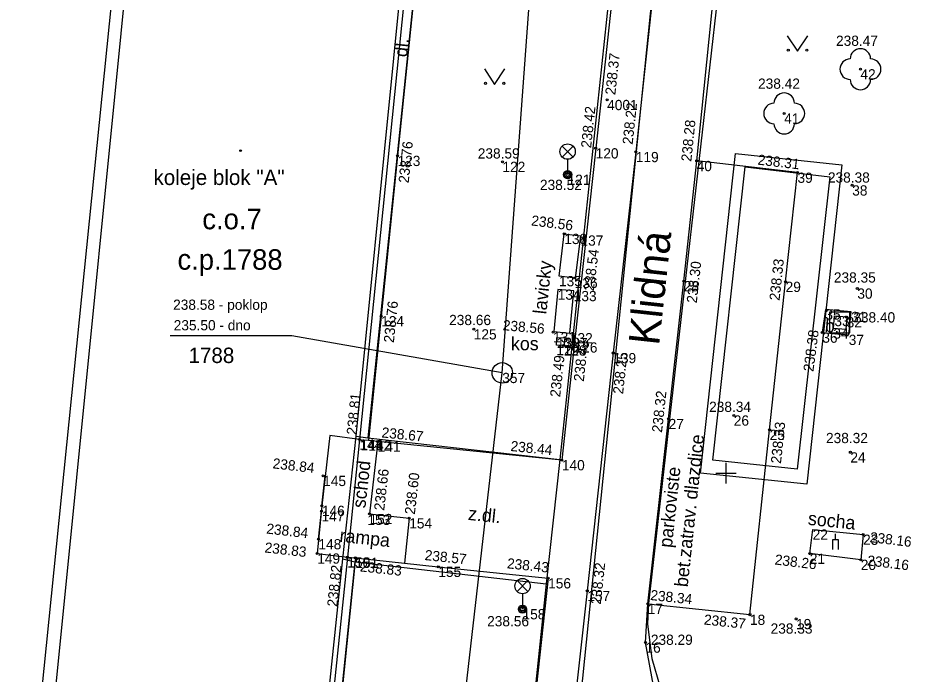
# Model space of a CAD drawing. Extents: x -596309 to -596099, y -1158697 to -1158513.
# Drawn here: x -596284.56 to -596240.96, y -1158609.82 to -1158577.76 of the extents above; entities that cross this region are included whole.
import ezdxf

# ---------------------------------------------------------------- set-up
doc = ezdxf.new("R2010")
doc.units = 0
for name, color, linetype in [('Vrstva 1', 7, 'Continuous'), ('Vrstva 10', 7, 'Continuous'), ('Vrstva 11', 7, 'Continuous'), ('Vrstva 14', 7, 'Continuous'), ('Vrstva 2', 7, 'Continuous'), ('Vrstva 22', 7, 'Continuous'), ('Vrstva 26', 7, 'Continuous'), ('Vrstva 27', 7, 'Continuous'), ('Vrstva 3', 7, 'Continuous'), ('Vrstva 33', 7, 'Continuous'), ('Vrstva 36', 7, 'Continuous'), ('Vrstva 38', 7, 'Continuous'), ('Vrstva 39', 7, 'Continuous'), ('Vrstva 40', 7, 'Continuous'), ('Vrstva 41', 7, 'Continuous'), ('Vrstva 46', 7, 'Continuous'), ('Vrstva 47', 7, 'Continuous'), ('Vrstva 49', 7, 'Continuous'), ('Vrstva 5', 7, 'Continuous'), ('Vrstva 58', 7, 'Continuous'), ('Vrstva 59', 7, 'Continuous'), ('Vrstva 60', 7, 'Continuous'), ('Vrstva 61', 7, 'Continuous'), ('Vrstva 8', 7, 'Continuous')]:
    doc.layers.add(name, color=color, linetype=linetype)

msp = doc.modelspace()

# ---------------------------------------------------------------- linework, layer by layer
at = {"layer": 'Vrstva 1'}
for p, q in [((-596284.56, -1158622.27), (-596277.87, -1158556.03)), ((-596263.44, -1158559.15), (-596267.48, -1158598.27)), ((-596254.63, -1158566.54), (-596258.11, -1158599.33)), ((-596252.59, -1158566.74), (-596260.61, -1158645.31)), ((-596253.77, -1158606.37), (-596250.06, -1158573.78)), ((-596251.25, -1158600), (-596249.54, -1158584.38)), ((-596249.54, -1158584.38), (-596244.34, -1158584.94)), ((-596250.64, -1158599.37), (-596249.07, -1158585.04)), ((-596249.07, -1158585.04), (-596244.94, -1158585.52)), ((-596244.34, -1158584.94), (-596246.05, -1158600.53)), ((-596244.94, -1158585.52), (-596246.53, -1158599.81)), ((-596268.05, -1158598.2), (-596267.48, -1158598.27)), ((-596267.48, -1158598.27), (-596258.11, -1158599.33)), ((-596258.11, -1158599.33), (-596258.77, -1158605.41)), ((-596246.53, -1158599.81), (-596250.64, -1158599.37)), ((-596246.05, -1158600.53), (-596251.25, -1158600)), ((-596268.11, -1158604.33), (-596270.4, -1158626.69)), ((-596268.7, -1158604.18), (-596268.11, -1158604.33)), ((-596268.11, -1158604.33), (-596258.77, -1158605.41)), ((-596258.77, -1158605.41), (-596262.89, -1158644.39)), ((-596253.81, -1158607.36), (-596253.77, -1158606.37)), ((-596253.61, -1158609.06), (-596253.81, -1158607.36)), ((-596253.2, -1158610.47), (-596253.61, -1158609.06))]:
    msp.add_line(p, q, dxfattribs=at)
msp.add_lwpolyline([(-596270.97, -1158626.01), (-596268.7, -1158604.18), (-596268.05, -1158598.2), (-596264.37, -1158561.26), (-596268.27, -1158560.79), (-596268.03, -1158558.14), (-596277.39, -1158556.98), (-596283.84, -1158621.73)], dxfattribs=at)
at = {"layer": 'Vrstva 10'}
for points in [[(-596255.23, -1158545.06), (-596254.2, -1158547.01), (-596253.17, -1158550.76), (-596252.36, -1158555.01), (-596251.99, -1158558.97), (-596251.94, -1158561.36), (-596252.44, -1158566.04), (-596253.24, -1158573.57), (-596254.4, -1158584.31), (-596255.5, -1158594.13), (-596256.77, -1158605.75), (-596257.81, -1158615.11), (-596258.65, -1158622.97), (-596259.56, -1158631.31), (-596260.07, -1158635.97)], [(-596253.51, -1158610.57), (-596253.93, -1158608.27), (-596253.82, -1158606.38), (-596248.83, -1158606.91), (-596247.87, -1158597.88), (-596247.09, -1158590.65), (-596246.51, -1158585.32), (-596251.43, -1158584.75), (-596250.33, -1158573.96), (-596250.2, -1158572.65), (-596249.12, -1158563.05), (-596248.35, -1158556.12), (-596248.08, -1158555.05), (-596247.42, -1158553.82), (-596246.81, -1158553.02), (-596245.52, -1158551.57), (-596243.33, -1158550.18), (-596240.98, -1158549.46)]]:
    msp.add_lwpolyline(points, dxfattribs=at)
at = {"layer": 'Vrstva 11'}
for p, q in [((-596267.45, -1158598.4), (-596267.84, -1158598.38)), ((-596265.46, -1158602.2), (-596265.697, -1158604.39)), ((-596268.48, -1158604.11), (-596268.09, -1158604.13))]:
    msp.add_line(p, q, dxfattribs=at)
for points in [[(-596264.269, -1158561.096), (-596264.23, -1158559.86), (-596261.45, -1158560.17), (-596260.93, -1158560.92), (-596259.93, -1158560.98), (-596259.85, -1158560.33), (-596254.02, -1158560.92), (-596254.46, -1158565.92), (-596255.2, -1158573.41), (-596256.36, -1158584.13), (-596257.39, -1158593.61), (-596258.01, -1158599.36), (-596267, -1158598.45), (-596267.45, -1158598.4)], [(-596264.12, -1158561.11), (-596263.62, -1158561.23), (-596264.07, -1158565.05), (-596264.83, -1158572.78), (-596266.03, -1158584.5), (-596266.83, -1158592.33), (-596267.45, -1158598.4)], [(-596253.82, -1158606.38), (-596252.8, -1158597.35), (-596252.06, -1158590.62), (-596251.43, -1158584.75)], [(-596267, -1158598.45), (-596267.4, -1158601.99), (-596265.46, -1158602.2)], [(-596268.09, -1158604.13), (-596269.05, -1158613.79), (-596269.79, -1158621.23), (-596270.48, -1158628.13), (-596269.54, -1158628.22), (-596270.08, -1158633.46)], [(-596268.09, -1158604.13), (-596264.04, -1158604.57), (-596258.68, -1158605.13), (-596259.74, -1158614.86), (-596260.55, -1158622.72), (-596261.59, -1158631.85), (-596261.81, -1158634.02), (-596262.2, -1158634.28), (-596265.1, -1158634.02), (-596270.08, -1158633.46)]]:
    msp.add_lwpolyline(points, dxfattribs=at)
for points in [[(-596258.15, -1158590.37), (-596257.89, -1158588.31), (-596257.102, -1158588.409), (-596257.362, -1158590.469)], [(-596257.62, -1158593.16), (-596257.43, -1158591.1), (-596258.21, -1158591.028), (-596258.4, -1158593.088)], [(-596243.89, -1158592.12), (-596245.15, -1158592), (-596245.3, -1158593.13), (-596244.01, -1158593.24)], [(-596257.87, -1158593.39), (-596257.92, -1158593.76), (-596258.28, -1158593.74), (-596258.26, -1158593.38)], [(-596243.42, -1158604.23), (-596245.91, -1158603.93), (-596245.77, -1158602.75), (-596243.31, -1158603)]]:
    msp.add_lwpolyline(points, close=True, dxfattribs=at)
at = {"layer": 'Vrstva 2'}
msp.add_lwpolyline([(-596260.92, -1158595.1), (-596271.183, -1158593.285), (-596277.122, -1158593.285)], dxfattribs=at)
for centre in [(-596243.44, -1158580.27), (-596255.8, -1158581.77), (-596247.16, -1158582.43), (-596266.03, -1158584.5), (-596256.36, -1158584.13), (-596254.4, -1158584.31), (-596260.91, -1158584.79), (-596251.43, -1158584.75), (-596246.51, -1158585.32), (-596243.84, -1158585.94), (-596257.89, -1158588.31), (-596257.38, -1158590.46), (-596252.06, -1158590.62), (-596247.09, -1158590.65), (-596243.59, -1158590.98), (-596266.83, -1158592.33), (-596244.11, -1158592.38), (-596262.31, -1158592.97), (-596258.44, -1158593.11), (-596245.3, -1158593.13), (-596257.39, -1158593.61), (-596257.92, -1158593.76), (-596255.5, -1158594.13), (-596252.8, -1158597.35), (-596249.62, -1158597.18), (-596247.87, -1158597.88), (-596267.89, -1158598.35), (-596267, -1158598.45), (-596243.93, -1158598.98), (-596258.01, -1158599.36), (-596269.66, -1158600.13), (-596269.74, -1158601.86), (-596269.72, -1158601.59), (-596267.4, -1158601.99), (-596265.46, -1158602.2), (-596269.89, -1158603.22), (-596243.31, -1158603), (-596269.95, -1158603.92), (-596268.48, -1158604.11), (-596268.09, -1158604.13), (-596245.91, -1158603.93), (-596264.04, -1158604.57), (-596243.42, -1158604.23), (-596258.68, -1158605.13), (-596256.77, -1158605.75), (-596253.82, -1158606.38), (-596248.83, -1158606.91), (-596246.58, -1158607.12), (-596253.93, -1158608.27)]:
    msp.add_circle(centre, 0.05, dxfattribs=at)
at = {"layer": 'Vrstva 22'}
for centre in [(-596243.44, -1158580.27), (-596247.16, -1158582.43)]:
    msp.add_circle(centre, 0.05, dxfattribs=at)
for centre, start, end in [((-596243.44, -1158579.77), 0, 180), ((-596243.94, -1158580.27), 90, 270), ((-596242.94, -1158580.27), 270, 90), ((-596243.44, -1158580.77), 180, 0), ((-596247.16, -1158581.93), 0, 180), ((-596247.66, -1158582.43), 90, 270), ((-596246.66, -1158582.43), 270, 90), ((-596247.16, -1158582.93), 180, 0)]:
    msp.add_arc(centre, 0.5, start, end, dxfattribs=at)
at = {"layer": 'Vrstva 26'}
msp.add_lwpolyline([(-596244.955, -1158593.14), (-596243.955, -1158593.14), (-596243.955, -1158592.14), (-596244.955, -1158592.14)], close=True, dxfattribs=at)
at = {"layer": 'Vrstva 27'}
msp.add_circle((-596260.92, -1158595.1), 0.5, dxfattribs=at)
at = {"layer": 'Vrstva 3'}
for p, q in [((-596243.44, -1158580.27), (-596243.439, -1158580.27)), ((-596255.8, -1158581.77), (-596255.799, -1158581.77)), ((-596247.16, -1158582.43), (-596247.159, -1158582.43)), ((-596256.36, -1158584.13), (-596256.359, -1158584.13)), ((-596254.4, -1158584.31), (-596254.399, -1158584.31)), ((-596266.03, -1158584.5), (-596266.029, -1158584.5)), ((-596260.91, -1158584.79), (-596260.909, -1158584.79)), ((-596251.43, -1158584.75), (-596251.429, -1158584.75)), ((-596246.51, -1158585.32), (-596246.509, -1158585.32)), ((-596257.73, -1158585.42), (-596257.729, -1158585.42)), ((-596243.84, -1158585.94), (-596243.839, -1158585.94)), ((-596257.89, -1158588.31), (-596257.889, -1158588.31)), ((-596257.1, -1158588.39), (-596257.099, -1158588.39)), ((-596258.15, -1158590.37), (-596258.149, -1158590.37)), ((-596257.38, -1158590.46), (-596257.379, -1158590.46)), ((-596252.06, -1158590.62), (-596252.059, -1158590.62)), ((-596247.09, -1158590.65), (-596247.089, -1158590.65)), ((-596243.59, -1158590.98), (-596243.589, -1158590.98)), ((-596258.21, -1158591.03), (-596258.209, -1158591.03)), ((-596257.43, -1158591.1), (-596257.429, -1158591.1)), ((-596245.15, -1158592), (-596245.149, -1158592)), ((-596243.89, -1158592.12), (-596243.889, -1158592.12)), ((-596266.83, -1158592.33), (-596266.829, -1158592.33)), ((-596244.71, -1158592.32), (-596244.709, -1158592.32)), ((-596244.11, -1158592.38), (-596244.109, -1158592.38)), ((-596262.31, -1158592.97), (-596262.309, -1158592.97)), ((-596258.44, -1158593.11), (-596258.439, -1158593.11)), ((-596257.62, -1158593.16), (-596257.619, -1158593.16)), ((-596245.3, -1158593.13), (-596245.299, -1158593.13)), ((-596244.76, -1158592.93), (-596244.759, -1158592.93)), ((-596258.26, -1158593.38), (-596258.259, -1158593.38)), ((-596257.87, -1158593.39), (-596257.869, -1158593.39)), ((-596257.39, -1158593.61), (-596257.389, -1158593.61)), ((-596244.01, -1158593.24), (-596244.009, -1158593.24)), ((-596258.28, -1158593.74), (-596258.279, -1158593.74)), ((-596257.92, -1158593.76), (-596257.919, -1158593.76)), ((-596255.5, -1158594.13), (-596255.499, -1158594.13)), ((-596260.92, -1158595.1), (-596260.919, -1158595.1)), ((-596260.92, -1158595.1), (-596260.919, -1158595.1)), ((-596252.8, -1158597.35), (-596252.799, -1158597.35)), ((-596249.62, -1158597.18), (-596249.619, -1158597.18)), ((-596247.87, -1158597.88), (-596247.869, -1158597.88)), ((-596267.89, -1158598.35), (-596267.889, -1158598.35)), ((-596267.84, -1158598.38), (-596267.839, -1158598.38)), ((-596267.45, -1158598.4), (-596267.449, -1158598.4)), ((-596267, -1158598.45), (-596266.999, -1158598.45)), ((-596243.93, -1158598.98), (-596243.929, -1158598.98)), ((-596258.01, -1158599.36), (-596258.009, -1158599.36)), ((-596269.66, -1158600.13), (-596269.659, -1158600.13)), ((-596269.74, -1158601.86), (-596269.739, -1158601.86)), ((-596269.72, -1158601.59), (-596269.719, -1158601.59)), ((-596267.5, -1158602.03), (-596267.499, -1158602.03)), ((-596267.4, -1158601.99), (-596267.399, -1158601.99)), ((-596265.46, -1158602.2), (-596265.459, -1158602.2)), ((-596245.77, -1158602.75), (-596245.769, -1158602.75)), ((-596243.31, -1158603), (-596243.309, -1158603)), ((-596269.89, -1158603.22), (-596269.889, -1158603.22)), ((-596269.95, -1158603.92), (-596269.949, -1158603.92)), ((-596245.91, -1158603.93), (-596245.909, -1158603.93)), ((-596268.48, -1158604.11), (-596268.479, -1158604.11)), ((-596268.09, -1158604.13), (-596268.089, -1158604.13)), ((-596243.42, -1158604.23), (-596243.419, -1158604.23)), ((-596264.04, -1158604.57), (-596264.039, -1158604.57)), ((-596258.68, -1158605.13), (-596258.679, -1158605.13)), ((-596256.77, -1158605.75), (-596256.769, -1158605.75)), ((-596259.93, -1158606.64), (-596259.929, -1158606.64)), ((-596253.82, -1158606.38), (-596253.819, -1158606.38)), ((-596248.83, -1158606.91), (-596248.829, -1158606.91)), ((-596246.58, -1158607.12), (-596246.579, -1158607.12)), ((-596253.93, -1158608.27), (-596253.929, -1158608.27))]:
    msp.add_line(p, q, dxfattribs=at)
at = {"layer": 'Vrstva 33'}
for p, q in [((-596257.995, -1158584.56), (-596257.465, -1158584.03)), ((-596257.995, -1158584.03), (-596257.465, -1158584.56)), ((-596257.73, -1158584.67), (-596257.73, -1158585.42)), ((-596260.195, -1158605.78), (-596259.665, -1158605.25)), ((-596260.195, -1158605.25), (-596259.665, -1158605.78)), ((-596259.93, -1158605.89), (-596259.93, -1158606.64))]:
    msp.add_line(p, q, dxfattribs=at)
for centre, radius in [((-596257.73, -1158584.295), 0.375), ((-596257.73, -1158585.42), 0.2), ((-596257.73, -1158585.42), 0.145), ((-596257.73, -1158585.42), 0.0876), ((-596259.93, -1158605.515), 0.375), ((-596259.93, -1158606.64), 0.2), ((-596259.93, -1158606.64), 0.145), ((-596259.93, -1158606.64), 0.0876)]:
    msp.add_circle(centre, radius, dxfattribs=at)
at = {"layer": 'Vrstva 36'}
for points in [[(-596247.008, -1158578.638), (-596246.508, -1158579.388), (-596246.008, -1158578.638)], [(-596261.79, -1158580.259), (-596261.29, -1158581.009), (-596260.79, -1158580.259)]]:
    msp.add_lwpolyline(points, dxfattribs=at)
for centre in [(-596246.959, -1158579.338), (-596246.059, -1158579.338), (-596261.74, -1158580.959), (-596260.841, -1158580.959)]:
    msp.add_circle(centre, 0.05, dxfattribs=at)
at = {"layer": 'Vrstva 38'}
msp.add_line((-596244.654, -1158603.233), (-596244.654, -1158602.968), dxfattribs=at)
msp.add_lwpolyline([(-596244.779, -1158603.733), (-596244.779, -1158603.233), (-596244.529, -1158603.233), (-596244.529, -1158603.733)], dxfattribs=at)
at = {"layer": 'Vrstva 39'}
for radius in [0.045, 0.0199]:
    msp.add_circle((-596273.69, -1158584.248), radius, dxfattribs=at)
at = {"layer": 'Vrstva 5'}
msp.add_line((-596267.89, -1158598.35), (-596268.48, -1158604.11), dxfattribs=at)
msp.add_lwpolyline([(-596269.438, -1158560.623), (-596264.12, -1158561.11), (-596267.89, -1158598.35), (-596269.33, -1158598.167), (-596269.72, -1158601.59), (-596269.95, -1158603.92), (-596268.48, -1158604.11), (-596270.74, -1158625.83), (-596270.81, -1158625.81), (-596271.53, -1158633.35), (-596276.188, -1158632.886)], dxfattribs=at)
at = {"layer": 'Vrstva 58'}
msp.add_lwpolyline([(-596244.76, -1158592.93), (-596244.71, -1158592.32), (-596244.109, -1158592.369), (-596244.159, -1158592.979)], close=True, dxfattribs=at)
at = {"layer": 'Vrstva 60'}
msp.add_lwpolyline([(-596247.668, -1158643.114), (-596265.091, -1158631.45), (-596260.921, -1158595.1), (-596258.491, -1158561.83), (-596276.3, -1158553.438)], dxfattribs=at)
at = {"layer": 'Vrstva 61'}
for p, q in [((-596250, -1158599.5), (-596250, -1158600.5)), ((-596250.5, -1158600), (-596249.5, -1158600))]:
    msp.add_line(p, q, dxfattribs=at)
at = {"layer": 'Vrstva 8'}
for p, q in [((-596269.72, -1158601.59), (-596269.56, -1158600.138)), ((-596269.89, -1158603.22), (-596269.74, -1158601.86))]:
    msp.add_line(p, q, dxfattribs=at)

# ---------------------------------------------------------------- texts
at = {"layer": 'Vrstva 1'}
msp.add_text('357', height=0.5, dxfattribs=at).set_placement((-596260.92, -1158595.6))
at = {"layer": 'Vrstva 14'}
msp.add_text('1788', height=0.75, dxfattribs=at).set_placement((-596276.23, -1158594.62))
at = {"layer": 'Vrstva 2'}
for s, p in [('238.47', (-596244.63, -1158579.13)), ('238.42', (-596248.436, -1158581.225)), ('238.59', (-596262.114, -1158584.633)), ('238.38', (-596245.026, -1158585.808)), ('238.52', (-596259.08, -1158586.17)), ('238.35', (-596244.735, -1158590.691)), ('238.58 - poklop', (-596276.983, -1158592.022)), ('238.66', (-596263.512, -1158592.768)), ('238.40', (-596243.789, -1158592.64)), ('235.50 - dno', (-596276.954, -1158593.024)), ('238.34', (-596250.824, -1158597.007)), ('238.32', (-596245.12, -1158598.533)), ('238.56', (-596261.657, -1158607.481)), ('238.33', (-596247.823, -1158607.838)), ('238.29', (-596253.666, -1158608.385))]:
    msp.add_text(s, height=0.5, dxfattribs=at).set_placement(p)
for s, rotation, p in [('238.37', 83.8241, (-596255.403, -1158581.546)), ('238.42', 83.8241, (-596256.586, -1158584.141)), ('238.22', 83.8355, (-596254.559, -1158583.968)), ('238.28', 84.179, (-596251.693, -1158584.801)), ('238.76', 84.1663, (-596265.488, -1158585.852)), ('238.31', 353.3915, (-596248.475, -1158584.928)), ('238.56', 352.8065, (-596259.527, -1158587.896)), ('238.54', 82.8065, (-596256.455, -1158591.12)), ('238.30', 83.7252, (-596251.428, -1158591.712)), ('238.33', 83.8425, (-596247.389, -1158591.592)), ('238.76', 84.1679, (-596266.21, -1158593.649)), ('238.56', 354.7303, (-596260.911, -1158593.011)), ('238.38', 82.4386, (-596245.737, -1158595.062)), ('238.42', 83.8458, (-596256.941, -1158595.543)), ('238.49', 83.8458, (-596258.095, -1158596.304)), ('238.25', 83.7627, (-596255.025, -1158596.156)), ('238.81', 84.2193, (-596268.025, -1158598.148)), ('238.32', 83.7252, (-596253.125, -1158598.036)), ('238.33', 83.9315, (-596247.319, -1158599.555)), ('238.67', 354.22, (-596266.826, -1158598.252)), ('238.44', 354.22, (-596260.534, -1158598.915)), ('238.84', 353.4998, (-596272.146, -1158599.761)), ('238.66', 83.5532, (-596266.683, -1158601.848)), ('238.60', 83.5532, (-596265.187, -1158602.037)), ('238.84', 353.4998, (-596272.452, -1158602.946)), ('238.16', 353.13, (-596243.001, -1158603.364)), ('238.83', 353.4998, (-596272.538, -1158603.869)), ('238.57', 354.0355, (-596264.722, -1158604.24)), ('238.26', 353.13, (-596247.64, -1158604.458)), ('238.16', 353.13, (-596243.131, -1158604.503)), ('238.82', 84.0597, (-596268.972, -1158606.546)), ('238.83', 353.7996, (-596267.881, -1158604.796)), ('238.43', 354.0355, (-596260.707, -1158604.644)), ('238.32', 83.7627, (-596256.114, -1158606.427)), ('238.34', 353.9372, (-596253.711, -1158606.192)), ('238.37', 353.9372, (-596251.096, -1158607.39))]:
    msp.add_text(s, height=0.5, rotation=rotation, dxfattribs=at).set_placement(p)
at = {"layer": 'Vrstva 40'}
for s, rotation, p in [('dl.', 84.1539, (-596265.564, -1158579.697)), ('lavicky', 83.7991, (-596258.772, -1158592.256)), ('b.', 355.1261, (-596245.195, -1158593.101)), ('bet.zatrav. dlazdice', 83.8425, (-596251.871, -1158605.585)), ('schod', 83.5532, (-596267.603, -1158601.731)), ('parkoviste', 83.8425, (-596252.642, -1158603.663)), ('z.dl.', 354.0284, (-596262.612, -1158602.28)), ('socha', 354.0284, (-596246.023, -1158602.519)), ('rampa', 353.8219, (-596268.883, -1158603.345))]:
    msp.add_text(s, height=0.65, rotation=rotation, dxfattribs=at).set_placement(p)
msp.add_text('kos', height=0.65, dxfattribs=at).set_placement((-596260.495, -1158593.997))
at = {"layer": 'Vrstva 41'}
msp.add_text('koleje blok "A"', height=0.75, dxfattribs=at).set_placement((-596277.94, -1158585.926))
at = {"layer": 'Vrstva 46'}
msp.add_text('c.o.7', height=1, dxfattribs=at).set_placement((-596275.558, -1158588.088))
at = {"layer": 'Vrstva 47'}
msp.add_text('c.p.1788', height=1, dxfattribs=at).set_placement((-596276.77, -1158590.064))
at = {"layer": 'Vrstva 49'}
msp.add_text('Klidná', height=1.5, rotation=83.7627, dxfattribs=at).set_placement((-596253.268, -1158593.798))
at = {"layer": 'Vrstva 59'}
for s, p in [('42', (-596243.44, -1158580.77)), ('4001', (-596255.8, -1158582.27)), ('41', (-596247.16, -1158582.93)), ('120', (-596256.36, -1158584.63)), ('119', (-596254.4, -1158584.81)), ('123', (-596266.03, -1158585)), ('122', (-596260.91, -1158585.29)), ('40', (-596251.43, -1158585.25)), ('39', (-596246.51, -1158585.82)), ('121', (-596257.73, -1158585.92)), ('38', (-596243.84, -1158586.44)), ('138', (-596257.89, -1158588.81)), ('137', (-596257.1, -1158588.89)), ('135', (-596258.15, -1158590.87)), ('136', (-596257.38, -1158590.96)), ('28', (-596252.06, -1158591.12)), ('29', (-596247.09, -1158591.15)), ('30', (-596243.59, -1158591.48)), ('134', (-596258.21, -1158591.53)), ('133', (-596257.43, -1158591.6)), ('35', (-596245.15, -1158592.5)), ('33', (-596244.71, -1158592.82)), ('31', (-596243.89, -1158592.62)), ('124', (-596266.83, -1158592.83)), ('32', (-596244.11, -1158592.88)), ('125', (-596262.31, -1158593.47)), ('131', (-596258.44, -1158593.61)), ('132', (-596257.62, -1158593.66)), ('36', (-596245.3, -1158593.63)), ('34', (-596244.76, -1158593.43)), ('130', (-596258.26, -1158593.88)), ('127', (-596257.87, -1158593.89)), ('126', (-596257.39, -1158594.11)), ('37', (-596244.01, -1158593.74)), ('129', (-596258.28, -1158594.24)), ('128', (-596257.92, -1158594.26)), ('139', (-596255.5, -1158594.63)), ('27', (-596252.8, -1158597.85)), ('26', (-596249.62, -1158597.68)), ('25', (-596247.87, -1158598.38)), ('144', (-596267.89, -1158598.85)), ('143', (-596267.84, -1158598.88)), ('142', (-596267.45, -1158598.9)), ('141', (-596267, -1158598.95)), ('24', (-596243.93, -1158599.48)), ('140', (-596258.01, -1158599.86)), ('145', (-596269.66, -1158600.63)), ('147', (-596269.74, -1158602.36)), ('146', (-596269.72, -1158602.09)), ('153', (-596267.5, -1158602.53)), ('152', (-596267.4, -1158602.49)), ('154', (-596265.46, -1158602.7)), ('22', (-596245.77, -1158603.25)), ('148', (-596269.89, -1158603.72)), ('23', (-596243.31, -1158603.5)), ('149', (-596269.95, -1158604.42)), ('21', (-596245.91, -1158604.43)), ('150', (-596268.48, -1158604.61)), ('151', (-596268.09, -1158604.63)), ('20', (-596243.42, -1158604.73)), ('155', (-596264.04, -1158605.07)), ('156', (-596258.68, -1158605.63)), ('157', (-596256.77, -1158606.25)), ('158', (-596259.93, -1158607.14)), ('17', (-596253.82, -1158606.88)), ('18', (-596248.83, -1158607.41)), ('19', (-596246.58, -1158607.62)), ('16', (-596253.93, -1158608.77))]:
    msp.add_text(s, height=0.5, dxfattribs=at).set_placement(p)

doc.saveas('drawing.dxf')
